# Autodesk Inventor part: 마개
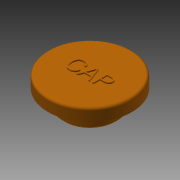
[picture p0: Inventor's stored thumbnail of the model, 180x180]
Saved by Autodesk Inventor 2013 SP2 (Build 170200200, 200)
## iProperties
Created: 2018-03
Part Number: 마개
Material: 고무
Document SubType Name: Modeling
Designer: mduedu
Density: 1 g/cm^3
Author: mduedu
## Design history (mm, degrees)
sketch "스케치1"
  geometry: C1 r 17 at (0, 0); 1 further point
  constraints: 1 centre point, 1 coincident
  dimensions: "d21" = 34 diameter of C1
extrude "돌출1" new body sketch "스케치1" distance "d2" = 6; taper "d3" = 0 deg
fillet "모깎기4" dims "d22" = 1
sketch "스케치6"
  geometry: C1 r 11 at (0, 0); 1 further point
  constraints: 1 centre point, 1 coincident
  dimensions: "d23" = 22 diameter of C1
extrude "돌출5" join sketch "스케치6" distance "d24" = 6; taper "d25" = 0 deg
sketch "스케치7"
  geometry: C1 r 7.5 at (0, 0); 1 further point
  constraints: 1 centre point, 1 coincident
  dimensions: "d26" = 15 diameter of C1
extrude "돌출6" cut sketch "스케치7" distance "d27" = 6; taper "d28" = 0 deg
sketch "스케치8"
  geometry: C1 r 17 at (0, 0) reference; C2 r 14 at (0, 0); 1 further point
  constraints: 1 centre point, 1 coincident
  dimensions: "d37" = 28 diameter of C2
extrude "돌출7" cut sketch "스케치8" distance "d30" = 1; taper "d31" = 0 deg
fillet "모깎기5" dims "d32" = 1
chamfer "모따기2" distance "d33" = 1; stored, may be unused: second distance "d34" = 2, angle "d35" = 45 deg
sketch "스케치5"
  geometry: 2 further points
  constraints: 1 coincident, 1 other
feature "엠보싱1" sketch "스케치5" dims "d19" = 0.5, "d20" = 0
node "솔리드1"
